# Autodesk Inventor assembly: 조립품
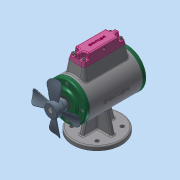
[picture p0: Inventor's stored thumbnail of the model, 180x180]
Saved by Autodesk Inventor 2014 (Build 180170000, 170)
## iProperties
Created: 2023-01
Part Number: 조립품
Document SubType Name: Assembly
Designer: dg
Mass: 3179.6 g
Surface Area: 2659.33 cm^2
Volume: 946.001 cm^3
Density: 3.3611 g/cm^3
Author: dg
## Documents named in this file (19)
- C:\Users\dg\Downloads\630106V1020\조립품.iam
- C:\Users\dg\Downloads\630106V1020\본체.ipt
- C:\Users\dg\Downloads\630106V1020\가변스프링.ipt
- C:\Users\dg\Downloads\630106V1020\뒤커버.ipt
- C:\Users\dg\Downloads\630106V1020\멈춤나사 M4 x 8.ipt
- C:\Users\dg\Downloads\630106V1020\베어링 6203.ipt
- C:\Users\dg\Downloads\630106V1020\볼트 M4 x 12.ipt
- C:\Users\dg\Downloads\630106V1020\볼트 M4 x 16.ipt
- C:\Users\dg\Downloads\630106V1020\부시.ipt
- C:\Users\dg\Downloads\630106V1020\슬라이드.ipt
- C:\Users\dg\Downloads\630106V1020\앞커버.ipt
- C:\Users\dg\Downloads\630106V1020\오일실 17 30 8.ipt
- C:\Users\dg\Downloads\630106V1020\축.ipt
- C:\Users\dg\Downloads\630106V1020\키 5 x 5 x 18.ipt
- C:\Users\dg\Downloads\630106V1020\팬날개.ipt
- 팬날개.ipt
- C:\Users\dg\Downloads\630106V1020\헤더커버.ipt
- C:\Users\dg\Downloads\630106V1020\가변스프링2.ipt
- C:\Users\dg\Downloads\630106V1020\가변스프링3.ipt
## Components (4 placed, 4 different names)
1. 가변스프링:1
2. 가변스프링2:1
3. 가변스프링3:1
4. 헤더커버:1
